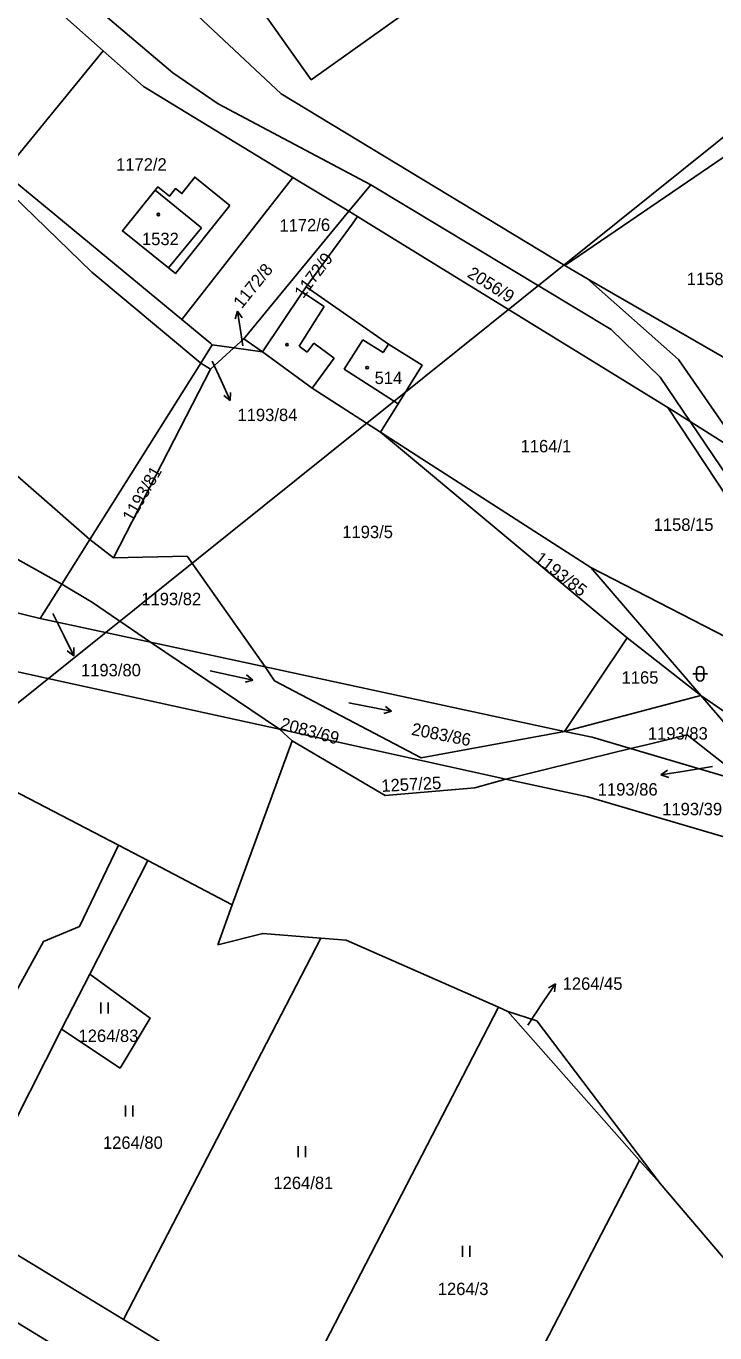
# Model space of a CAD drawing. Extents: x -793666 to -785424, y -1118958 to -1108761.
# Drawn here: x -792584 to -792489.4, y -1109962 to -1109782.8 of the extents above; entities that cross this region are included whole.
import ezdxf

# ---------------------------------------------------------------- set-up
doc = ezdxf.new("R2010")
doc.units = 0
for name, color, linetype in [('1_2000 - úřady', 7, 'Continuous'), ('Hranice parcel', 7, 'Continuous'), ('Parcelní čísla', 7, 'Continuous'), ('Pop  PČ popisy', 7, 'Continuous'), ('Vnitřní kresba', 7, 'Continuous'), ('Značky budov', 7, 'Continuous'), ('Značky kultur', 7, 'Continuous')]:
    doc.layers.add(name, color=color, linetype=linetype)

msp = doc.modelspace()

# ---------------------------------------------------------------- linework, layer by layer
at = {"layer": '1_2000 - úřady'}
msp.add_lwpolyline([(-791938.08, -1109742.36), (-792598.01, -1110271.46), (-792786.15, -1110036.8), (-792126.22, -1109507.7)], close=True, dxfattribs=at)
at = {"layer": 'Hranice parcel'}
for p, q in [((-792510.02, -1109815.62), (-792488.29, -1109800.79)), ((-792562.6, -1109823.02), (-792547.34, -1109803.55)), ((-792536.65, -1109804.52), (-792539.66, -1109808.17)), ((-792554.09, -1109825.67), (-792539.66, -1109808.17)), ((-792539.66, -1109808.17), (-792538.45, -1109808.89)), ((-792510.02, -1109815.62), (-792506.9, -1109817.42)), ((-792555.44, -1109826.91), (-792554.09, -1109825.67)), ((-792551.53, -1109827.43), (-792554.09, -1109825.67)), ((-792559.98, -1109829.02), (-792558.4, -1109826.51)), ((-792555.44, -1109826.91), (-792558.65, -1109829.85)), ((-792558.4, -1109826.51), (-792555.44, -1109826.91)), ((-792551.53, -1109827.43), (-792555.44, -1109826.91)), ((-792575.21, -1109853.19), (-792559.98, -1109829.02)), ((-792558.65, -1109829.85), (-792559.98, -1109829.02)), ((-792558.65, -1109829.85), (-792571.98, -1109855.72)), ((-792492.83, -1109837.02), (-792495.87, -1109835.1)), ((-792485.15, -1109841.88), (-792492.83, -1109837.02)), ((-792501.44, -1109866.68), (-792535.33, -1109838.48)), ((-792579.07, -1109859.32), (-792575.21, -1109853.19)), ((-792575.21, -1109853.19), (-792571.98, -1109855.72)), ((-792506.45, -1109857.05), (-792491.34, -1109874.62)), ((-792582.04, -1109864.04), (-792579.07, -1109859.32)), ((-792510.07, -1109879.52), (-792501.44, -1109866.68)), ((-792491.34, -1109874.62), (-792501.44, -1109866.68)), ((-792566.87, -1109867.3), (-792551.16, -1109870.68)), ((-792549.16, -1109879.23), (-792566.87, -1109867.3)), ((-792551.16, -1109870.68), (-792510.07, -1109879.52)), ((-792510.07, -1109879.52), (-792491.34, -1109874.62)), ((-792491.34, -1109874.62), (-792480.06, -1109887.74)), ((-792518.11, -1109886.06), (-792549.16, -1109879.23)), ((-792549.16, -1109879.23), (-792547.43, -1109880.8)), ((-792547.43, -1109880.8), (-792555.65, -1109903.32)), ((-792518.11, -1109886.06), (-792500.99, -1109881.89)), ((-792500.99, -1109881.89), (-792484.82, -1109886.64)), ((-792571.27, -1109895.13), (-792567.26, -1109897.24)), ((-792567.26, -1109897.24), (-792575.22, -1109912.84)), ((-792567.26, -1109897.24), (-792555.65, -1109903.32)), ((-792555.65, -1109903.32), (-792557.65, -1109908.8)), ((-792570.58, -1109960.21), (-792543.5, -1109907.88)), ((-792543.5, -1109907.88), (-792540.02, -1109908.16)), ((-792540.02, -1109908.16), (-792519.12, -1109917.38)), ((-792579.08, -1109920.4), (-792575.22, -1109912.84)), ((-792519.12, -1109917.38), (-792548.33, -1109973.78)), ((-792519.12, -1109917.38), (-792517.82, -1109917.95)), ((-792499.77, -1109938.38), (-792517.82, -1109917.95)), ((-792525.39, -1109987.79), (-792499.77, -1109938.38)), ((-792499.77, -1109938.38), (-792496.95, -1109941.57)), ((-792496.95, -1109941.57), (-792468.07, -1109975.45)), ((-792570.58, -1109960.21), (-792548.33, -1109973.78))]:
    msp.add_line(p, q, dxfattribs=at)
for points in [[(-792718.74, -1109582.83), (-792684.62, -1109620.8), (-792673.86, -1109638.49), (-792648.83, -1109676.6), (-792595.57, -1109748.42), (-792548.94, -1109792.07), (-792510.02, -1109815.62)], [(-792674.34, -1109647.36), (-792651.82, -1109684.77), (-792621.5, -1109724.44), (-792592.84, -1109761.47), (-792576.63, -1109778.3), (-792563.81, -1109789.18), (-792557.58, -1109793.43), (-792536.65, -1109804.52)], [(-792559.98, -1109829.02), (-792574.92, -1109816.54), (-792587.43, -1109804.4), (-792600.18, -1109786.49), (-792606.44, -1109777.45), (-792604.08, -1109769.83), (-792626.04, -1109748.8), (-792648.89, -1109725.85)], [(-792573.36, -1109786.15), (-792583.89, -1109776.79), (-792597.47, -1109762.19), (-792609.81, -1109746.62), (-792615.6, -1109738.9)], [(-792522.44, -1109761.43), (-792550.85, -1109781.64), (-792544.82, -1109790.11), (-792516.44, -1109769.89), (-792516.73, -1109769.48), (-792521.41, -1109763.02), (-792522.44, -1109761.43)], [(-792573.36, -1109786.15), (-792586.99, -1109802.83), (-792580.81, -1109807.95), (-792562.6, -1109823.02)], [(-792547.34, -1109803.55), (-792567.86, -1109791.03), (-792569.84, -1109789.27), (-792573.36, -1109786.15)], [(-792555.98, -1109807.36), (-792560.8, -1109803.47), (-792562.57, -1109805.74), (-792563.45, -1109805.05), (-792564.27, -1109806.08), (-792565.88, -1109804.82), (-792566.26, -1109805.29), (-792570.73, -1109810.86), (-792564.42, -1109815.93), (-792563.47, -1109816.69), (-792555.98, -1109807.36)], [(-792539.66, -1109808.17), (-792545.85, -1109804.46), (-792547.34, -1109803.55)], [(-792492.83, -1109837.02), (-792496.95, -1109830.93), (-792503.65, -1109824.38), (-792536.65, -1109804.52)], [(-792666.04, -1109812.15), (-792648.65, -1109814.21), (-792617.98, -1109830.19), (-792627.04, -1109809.49), (-792624.14, -1109808.65), (-792597.72, -1109833.53), (-792575.21, -1109853.19)], [(-792538.45, -1109808.89), (-792539.21, -1109809.93), (-792545.51, -1109818.52)], [(-792495.87, -1109835.1), (-792536.99, -1109809.8), (-792538.45, -1109808.89)], [(-792674.81, -1109815.08), (-792648.6, -1109842.28), (-792638.31, -1109851.89), (-792629.04, -1109859.12), (-792610.02, -1109865.87), (-792580.31, -1109872.39), (-792549.16, -1109879.23)], [(-792545.51, -1109818.52), (-792546.04, -1109819.25), (-792551.53, -1109827.43)], [(-792535.33, -1109838.48), (-792532.9, -1109834.58), (-792529.61, -1109829.28), (-792534.22, -1109826.38), (-792545.51, -1109818.52)], [(-792485.15, -1109841.88), (-792494.43, -1109828.49), (-792506.9, -1109817.42)], [(-792506.9, -1109817.42), (-792472.33, -1109837.37), (-792470.06, -1109834.57)], [(-792579.07, -1109859.32), (-792608.13, -1109843.03), (-792650.25, -1109821), (-792659.54, -1109818.98)], [(-792582.04, -1109864.04), (-792610.32, -1109857.13), (-792617.78, -1109854.53), (-792625.34, -1109851.04), (-792632.25, -1109846.43), (-792638.35, -1109841.01), (-792644.12, -1109835.18), (-792659.54, -1109818.98)], [(-792562.6, -1109823.02), (-792558.6, -1109826.33), (-792558.4, -1109826.51)], [(-792551.53, -1109827.43), (-792544.7, -1109832.44), (-792535.33, -1109838.48)], [(-792459.92, -1109888.82), (-792475.83, -1109865.41), (-792495.87, -1109835.1)], [(-792492.83, -1109837.02), (-792465.09, -1109878), (-792454.96, -1109888.96), (-792457.26, -1109890.78)], [(-792535.33, -1109838.48), (-792529.02, -1109842.55), (-792506.45, -1109857.05)], [(-792571.98, -1109855.72), (-792561.87, -1109855.49), (-792551.16, -1109870.68)], [(-792641.23, -1109857.76), (-792612.62, -1109873.62), (-792571.27, -1109895.13)], [(-792506.45, -1109857.05), (-792483.14, -1109869.01), (-792479.72, -1109872.05), (-792462.76, -1109889.76), (-792459.92, -1109888.82)], [(-792566.87, -1109867.3), (-792574.86, -1109861.84), (-792579.07, -1109859.32)], [(-792566.87, -1109867.3), (-792576.67, -1109865.19), (-792582.04, -1109864.04)], [(-792510.07, -1109879.52), (-792529.74, -1109883.15), (-792549.88, -1109872.57), (-792551.16, -1109870.68)], [(-792491.34, -1109874.62), (-792474.22, -1109886.31), (-792461.4, -1109894.05), (-792457.26, -1109890.78)], [(-792510.07, -1109879.52), (-792506.25, -1109880.34), (-792500.99, -1109881.89)], [(-792518.11, -1109886.06), (-792522.36, -1109887.29), (-792534.66, -1109888.31), (-792547.43, -1109880.8)], [(-792500.99, -1109881.89), (-792498.62, -1109881.31), (-792493.21, -1109880), (-792486.38, -1109885.41)], [(-792424.33, -1109945.11), (-792425.94, -1109943.64), (-792440.58, -1109930.57), (-792464.4, -1109909.3), (-792481.97, -1109895.81), (-792506.88, -1109888.52), (-792518.11, -1109886.06)], [(-792571.27, -1109895.13), (-792576.62, -1109906.28), (-792581.55, -1109908.33), (-792588.6, -1109921.1), (-792590.44, -1109924.67)], [(-792557.65, -1109908.8), (-792551.48, -1109907.24), (-792543.5, -1109907.88)], [(-792575.22, -1109912.84), (-792566.94, -1109918.85), (-792571.05, -1109925.71), (-792579.08, -1109920.4)], [(-792517.82, -1109917.95), (-792513.88, -1109919.24), (-792496.95, -1109941.57)], [(-792579.08, -1109920.4), (-792587.8, -1109937.48), (-792588.65, -1109939.86), (-792588.98, -1109942.89), (-792588.76, -1109944.93), (-792588.1, -1109947.35), (-792586.83, -1109949.39), (-792585.3, -1109951.24), (-792570.58, -1109960.21)], [(-792612.76, -1109985.21), (-792600.39, -1109961.31), (-792597.57, -1109958.68), (-792593.72, -1109957.43), (-792589.65, -1109957.94), (-792576, -1109966.26)]]:
    msp.add_lwpolyline(points, dxfattribs=at)
at = {"layer": 'Pop  PČ popisy'}
for p, q in [((-792554.92, -1109821.85), (-792555.27, -1109822.91)), ((-792554.5, -1109824.82), (-792554.92, -1109821.85)), ((-792554.92, -1109821.85), (-792554.28, -1109822.77)), ((-792554.23, -1109826.63), (-792554.5, -1109824.82)), ((-792558.4, -1109828.72), (-792557.18, -1109831.39)), ((-792557.18, -1109831.39), (-792555.96, -1109834.13)), ((-792555.96, -1109834.13), (-792556.82, -1109833.42)), ((-792555.96, -1109834.13), (-792555.91, -1109833.01)), ((-792580.27, -1109863.35), (-792578.74, -1109866.45)), ((-792578.74, -1109866.45), (-792577.42, -1109869.15)), ((-792577.42, -1109869.15), (-792578.31, -1109868.47)), ((-792577.42, -1109869.15), (-792577.41, -1109868.03)), ((-792496.82, -1109885.49), (-792495.91, -1109884.84)), ((-792489.73, -1109884.34), (-792493.86, -1109885.02)), ((-792493.86, -1109885.02), (-792496.82, -1109885.49)), ((-792496.82, -1109885.49), (-792495.76, -1109885.83)), ((-792512.98, -1109916.63), (-792511.3, -1109914.14)), ((-792511.3, -1109914.14), (-792512.28, -1109914.69)), ((-792511.3, -1109914.14), (-792511.45, -1109915.25)), ((-792515.1, -1109919.84), (-792512.98, -1109916.63))]:
    msp.add_line(p, q, dxfattribs=at)
at = {"layer": 'Vnitřní kresba'}
for p, q in [((-792566.26, -1109805.29), (-792559.89, -1109810.43)), ((-792559.89, -1109810.43), (-792564.42, -1109815.93)), ((-792546.04, -1109819.25), (-792543.05, -1109821.25)), ((-792543.05, -1109821.25), (-792546.48, -1109826.66)), ((-792546.48, -1109826.66), (-792545.36, -1109827.49)), ((-792545.36, -1109827.49), (-792544.45, -1109826.26)), ((-792544.45, -1109826.26), (-792541.68, -1109828.33)), ((-792537.72, -1109825.8), (-792540.3, -1109829.83)), ((-792534.95, -1109827.54), (-792537.72, -1109825.8)), ((-792534.22, -1109826.38), (-792534.95, -1109827.54)), ((-792541.68, -1109828.33), (-792544.7, -1109832.44)), ((-792540.3, -1109829.83), (-792532.9, -1109834.58))]:
    msp.add_line(p, q, dxfattribs=at)
at = {"layer": 'Značky budov'}
for centre in [(-792565.8, -1109808.61), (-792548.15, -1109826.47), (-792537.14, -1109829.62)]:
    msp.add_circle(centre, 0.175, dxfattribs=at)
at = {"layer": 'Značky kultur'}
for p, q in [((-792558.71, -1109871.23), (-792552.84, -1109872.48)), ((-792552.84, -1109872.48), (-792553.69, -1109871.78)), ((-792492.45, -1109871.62), (-792490.45, -1109871.62)), ((-792491.95, -1109871.12), (-792491.95, -1109872.12)), ((-792490.95, -1109872.12), (-792490.95, -1109871.12)), ((-792552.84, -1109872.48), (-792553.9, -1109872.76)), ((-792539.68, -1109875.63), (-792533.79, -1109876.77)), ((-792533.79, -1109876.77), (-792534.84, -1109877.08)), ((-792533.79, -1109876.77), (-792534.65, -1109876.09)), ((-792573.69, -1109918.24), (-792573.69, -1109916.74)), ((-792572.69, -1109918.24), (-792572.69, -1109916.74)), ((-792570.31, -1109932.34), (-792570.31, -1109930.84)), ((-792569.31, -1109932.34), (-792569.31, -1109930.84)), ((-792546.6, -1109937.93), (-792546.6, -1109936.43)), ((-792545.6, -1109937.93), (-792545.6, -1109936.43)), ((-792524.04, -1109951.61), (-792524.04, -1109950.11)), ((-792523.04, -1109951.61), (-792523.04, -1109950.11))]:
    msp.add_line(p, q, dxfattribs=at)
for centre, start, end in [((-792491.45, -1109871.12), 0, 180), ((-792491.45, -1109872.12), 180, 359.9879)]:
    msp.add_arc(centre, 0.5, start, end, dxfattribs=at)

# ---------------------------------------------------------------- texts
at = {"layer": 'Parcelní čísla'}
for s, p in [('1172/2', (-792571.61, -1109802.59)), ('1532', (-792568.05, -1109812.81)), ('1158/5', (-792493.29, -1109818.3)), ('514', (-792536.12, -1109831.87)), ('1193/84', (-792554.94, -1109836.95)), ('1164/1', (-792516.09, -1109841.24)), ('1158/15', (-792497.83, -1109852.01)), ('1193/5', (-792540.56, -1109853.01)), ('1193/82', (-792568.14, -1109862.21)), ('1193/80', (-792576.42, -1109871.97)), ('1165', (-792502.23, -1109872.98)), ('1193/83', (-792498.62, -1109880.65)), ('1193/86', (-792505.5, -1109888.33)), ('1193/39', (-792496.65, -1109891.03)), ('1264/45', (-792510.32, -1109914.98)), ('1264/83', (-792576.76, -1109922.14)), ('1264/80', (-792573.41, -1109936.8)), ('1264/81', (-792550.01, -1109942.32)), ('1264/3', (-792527.45, -1109956.86))]:
    msp.add_text(s, height=1.7, dxfattribs=at).set_placement(p)
for s, rotation, p in [('1172/6', 1, (-792549.17, -1109810.98)), ('1172/9', 53, (-792545.93, -1109820.23)), ('1172/8', 51, (-792554.35, -1109821.61)), ('2056/9', 328, (-792523.54, -1109817.1)), ('1193/81', 60, (-792569.37, -1109850.92)), ('1193/85', 322, (-792514.3, -1109856.08)), ('2083/69', 345, (-792549.2, -1109879.21)), ('2083/86', 349, (-792531.16, -1109879.99)), ('1257/25', 3, (-792535.15, -1109887.84))]:
    msp.add_text(s, height=1.7, rotation=rotation, dxfattribs=at).set_placement(p)

doc.saveas('drawing.dxf')
